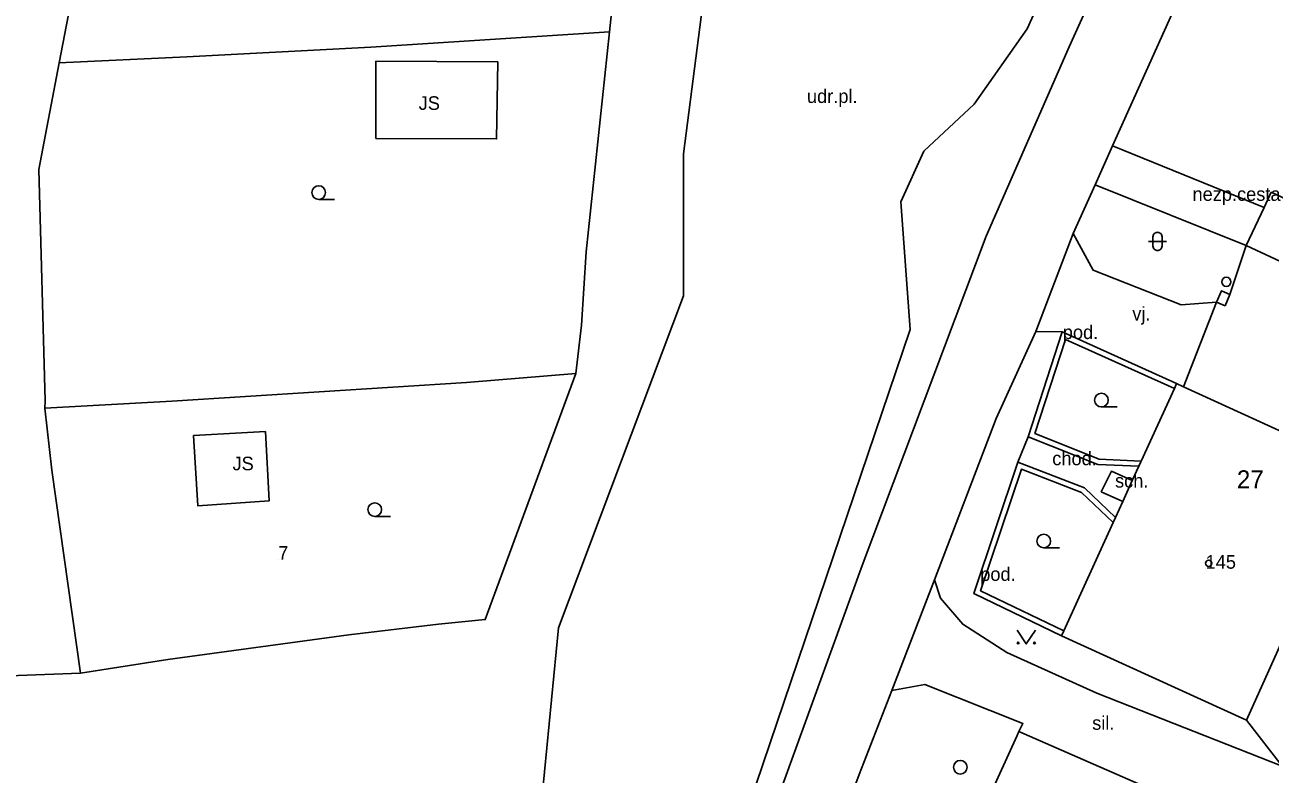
# Model space of a CAD drawing. Extents: x -836739 to -835945, y -1070775 to -1070126.
# Drawn here: x -836690.1 to -836621.5, y -1070440 to -1070398.7 of the extents above; entities that cross this region are included whole.
import ezdxf

# ---------------------------------------------------------------- set-up
doc = ezdxf.new("R2010")
doc.units = 0
for name, color, linetype in [('BodPole_mer', 7, 'Continuous'), ('Budovy_hranice', 7, 'Continuous'), ('Budovy_kody', 7, 'Continuous'), ('Doprava_hranice', 7, 'Continuous'), ('Doprava_kody', 7, 'Continuous'), ('OstPloch_kody', 7, 'Continuous'), ('PovrZnIS_body', 7, 'Continuous'), ('PovrZnIS_hranice', 7, 'Continuous'), ('RuianAdr_popis', 7, 'Continuous'), ('RuianPar_popis', 7, 'Continuous'), ('Stavby_hr_schod', 7, 'Continuous'), ('Stavby_hr_stav', 7, 'Continuous'), ('Stavby_kody', 7, 'Continuous'), ('Stavby_linie', 7, 'Continuous'), ('Zelen_kody', 7, 'Continuous')]:
    doc.layers.add(name, color=color, linetype=linetype)

msp = doc.modelspace()

# ---------------------------------------------------------------- linework, layer by layer
at = {"layer": 'BodPole_mer'}
for p, q in [((-836657.89, -1070399.1), (-836657.89, -1070399.1)), ((-836634.87, -1070398.93), (-836634.87, -1070398.93)), ((-836671.03, -1070399.94), (-836671.03, -1070399.94)), ((-836632.54, -1070399.93), (-836632.54, -1070399.93)), ((-836688.21, -1070400.8), (-836688.21, -1070400.8)), ((-836681.18, -1070400.48), (-836681.18, -1070400.48)), ((-836670.76, -1070400.72), (-836670.76, -1070400.72)), ((-836664.04, -1070400.76), (-836664.04, -1070400.76)), ((-836637.79, -1070403.09), (-836637.79, -1070403.09)), ((-836670.77, -1070404.97), (-836670.77, -1070404.97)), ((-836664.11, -1070405), (-836664.11, -1070405)), ((-836640.55, -1070405.67), (-836640.55, -1070405.67)), ((-836630.16, -1070405.38), (-836630.16, -1070405.38)), ((-836653.8, -1070405.82), (-836653.8, -1070405.82)), ((-836689.33, -1070406.69), (-836689.33, -1070406.69)), ((-836631.12, -1070407.53), (-836631.12, -1070407.53)), ((-836641.83, -1070408.47), (-836641.83, -1070408.47)), ((-836621.81, -1070408.77), (-836621.81, -1070408.77)), ((-836637.13, -1070410.36), (-836637.13, -1070410.36)), ((-836632.33, -1070410.21), (-836632.33, -1070410.21)), ((-836659.17, -1070411.22), (-836659.17, -1070411.22)), ((-836622.8, -1070410.87), (-836622.8, -1070410.87)), ((-836631.23, -1070412.22), (-836631.23, -1070412.22)), ((-836623.89, -1070412.87), (-836623.89, -1070412.87)), ((-836653.8, -1070413.64), (-836653.8, -1070413.64)), ((-836624.42, -1070413.99), (-836624.42, -1070413.99)), ((-836624.15, -1070413.36), (-836624.15, -1070413.36)), ((-836623.69, -1070413.56), (-836623.69, -1070413.56)), ((-836626.38, -1070414.14), (-836626.38, -1070414.14)), ((-836623.96, -1070414.19), (-836623.96, -1070414.19)), ((-836659.43, -1070415.26), (-836659.43, -1070415.26)), ((-836641.31, -1070415.5), (-836641.31, -1070415.5)), ((-836634.38, -1070415.61), (-836634.38, -1070415.61)), ((-836632.93, -1070415.63), (-836632.93, -1070415.63)), ((-836632.75, -1070416.04), (-836632.75, -1070416.04)), ((-836659.73, -1070417.92), (-836659.73, -1070417.92)), ((-836665.77, -1070418.42), (-836665.77, -1070418.42)), ((-836626.75, -1070418.74), (-836626.75, -1070418.74)), ((-836626.63, -1070418.47), (-836626.63, -1070418.47)), ((-836626.24, -1070418.65), (-836626.24, -1070418.65)), ((-836688.98, -1070419.42), (-836688.98, -1070419.42)), ((-836682, -1070419.45), (-836682, -1070419.45)), ((-836689, -1070419.82), (-836689, -1070419.82)), ((-836636.57, -1070420.39), (-836636.57, -1070420.39)), ((-836680.81, -1070421.34), (-836680.81, -1070421.34)), ((-836676.84, -1070421.11), (-836676.84, -1070421.11)), ((-836634.81, -1070421.4), (-836634.81, -1070421.4)), ((-836634.44, -1070421.22), (-836634.44, -1070421.22)), ((-836635.37, -1070422.8), (-836635.37, -1070422.8)), ((-836630.9, -1070422.63), (-836630.9, -1070422.63)), ((-836628.58, -1070422.74), (-836628.58, -1070422.74)), ((-836688.62, -1070423.25), (-836688.62, -1070423.25)), ((-836635.18, -1070423.19), (-836635.18, -1070423.19)), ((-836630.96, -1070422.93), (-836630.96, -1070422.93)), ((-836630.22, -1070423.3), (-836630.22, -1070423.3)), ((-836628.71, -1070423.03), (-836628.71, -1070423.03)), ((-836631.71, -1070424.21), (-836631.71, -1070424.21)), ((-836629.07, -1070423.82), (-836629.07, -1070423.82)), ((-836676.64, -1070424.93), (-836676.64, -1070424.93)), ((-836631.87, -1070424.47), (-836631.87, -1070424.47)), ((-836630.78, -1070424.43), (-836630.78, -1070424.43)), ((-836629.6, -1070424.97), (-836629.6, -1070424.97)), ((-836680.58, -1070425.2), (-836680.58, -1070425.2)), ((-836630.13, -1070426.13), (-836630.13, -1070426.13)), ((-836630, -1070425.84), (-836630, -1070425.84)), ((-836643.96, -1070428.49), (-836643.96, -1070428.49)), ((-836639.98, -1070429.29), (-836639.98, -1070429.29)), ((-836639.64, -1070430.3), (-836639.64, -1070430.3)), ((-836637.8, -1070430.04), (-836637.8, -1070430.04)), ((-836637.43, -1070429.88), (-836637.43, -1070429.88)), ((-836667.3, -1070431.72), (-836667.3, -1070431.72)), ((-836664.73, -1070431.47), (-836664.73, -1070431.47)), ((-836638.41, -1070431.73), (-836638.41, -1070431.73)), ((-836672.25, -1070432.32), (-836672.25, -1070432.32)), ((-836660.69, -1070431.93), (-836660.69, -1070431.93)), ((-836632.97, -1070432.36), (-836632.97, -1070432.36)), ((-836632.85, -1070432.09), (-836632.85, -1070432.09)), ((-836682.22, -1070433.67), (-836682.22, -1070433.67)), ((-836635.98, -1070433.29), (-836635.98, -1070433.29)), ((-836687.04, -1070434.42), (-836687.04, -1070434.42)), ((-836640.5, -1070435.05), (-836640.5, -1070435.05)), ((-836642.32, -1070435.38), (-836642.32, -1070435.38)), ((-836631.03, -1070435.52), (-836631.03, -1070435.52)), ((-836635.1, -1070437.2), (-836635.1, -1070437.2)), ((-836622.78, -1070437.01), (-836622.78, -1070437.01)), ((-836635.42, -1070437.86), (-836635.42, -1070437.86)), ((-836635.32, -1070437.63), (-836635.32, -1070437.63))]:
    msp.add_line(p, q, dxfattribs=at)
at = {"layer": 'Budovy_hranice'}
for p, q in [((-836632.97, -1070432.36), (-836622.78, -1070437.01)), ((-836622.29, -1070443.32), (-836635.32, -1070437.63))]:
    msp.add_line(p, q, dxfattribs=at)
for points in [[(-836626.63, -1070418.47), (-836626.75, -1070418.74), (-836628.58, -1070422.74), (-836628.71, -1070423.03), (-836629.07, -1070423.82), (-836629.6, -1070424.97), (-836630, -1070425.84), (-836630.13, -1070426.13), (-836632.85, -1070432.09), (-836632.97, -1070432.36)], [(-836616.52, -1070423.1), (-836626.24, -1070418.65), (-836626.63, -1070418.47)], [(-836616.52, -1070423.1), (-836616.66, -1070423.42), (-836618.95, -1070428.51), (-836619.49, -1070429.7), (-836622.78, -1070437.01)], [(-836635.32, -1070437.63), (-836635.42, -1070437.86), (-836637.6, -1070442.65), (-836637.7, -1070442.88), (-836637.98, -1070443.48)]]:
    msp.add_lwpolyline(points, dxfattribs=at)
at = {"layer": 'Budovy_kody'}
msp.add_circle((-836624.86, -1070428.37), 0.175, dxfattribs=at)
at = {"layer": 'Doprava_hranice'}
for p, q in [((-836621.81, -1070408.77), (-836630.16, -1070405.38)), ((-836622.8, -1070410.87), (-836631.12, -1070407.53)), ((-836632.93, -1070415.63), (-836634.38, -1070415.61))]:
    msp.add_line(p, q, dxfattribs=at)
for points in [[(-836637.13, -1070410.36), (-836632.54, -1070399.93), (-836624.1, -1070381.23), (-836615.6, -1070365.58), (-836607.14, -1070355.56), (-836596.81, -1070346.2), (-836590.03, -1070339.5), (-836589.31, -1070338.79), (-836589.07, -1070337.69), (-836589.06, -1070336.43), (-836589.28, -1070334.96), (-836590.73, -1070333.14), (-836591.73, -1070332.35), (-836593.66, -1070331.61), (-836605.86, -1070329.36), (-836624.31, -1070324.48)], [(-836629.46, -1070381.04), (-836630.1, -1070382.38), (-836632.83, -1070381.55), (-836636.09, -1070386.19), (-836641.48, -1070386.97), (-836650.79, -1070382.45), (-836653.8, -1070405.82), (-836653.8, -1070413.64), (-836660.69, -1070431.93), (-836661.86, -1070443.82), (-836659.27, -1070448.73), (-836656.69, -1070455.24), (-836654.9, -1070458.11)], [(-836626.49, -1070382.25), (-836628.93, -1070385.76), (-836634.87, -1070398.93), (-836637.79, -1070403.09), (-836640.55, -1070405.67), (-836641.83, -1070408.47), (-836641.31, -1070415.5), (-836651.36, -1070445.15), (-836654.9, -1070458.11), (-836657.15, -1070469.1)], [(-836636.57, -1070420.39), (-836634.38, -1070415.61), (-836632.33, -1070410.21), (-836631.12, -1070407.53), (-836630.16, -1070405.38), (-836624, -1070391.72)], [(-836649.35, -1070443.39), (-836643.96, -1070428.49), (-836637.13, -1070410.36)], [(-836624.42, -1070413.99), (-836626.38, -1070414.14), (-836631.23, -1070412.22), (-836632.33, -1070410.21)], [(-836636.57, -1070420.39), (-836639.98, -1070429.29), (-836642.32, -1070435.38), (-836644.12, -1070440), (-836644.66, -1070441.44), (-836645.98, -1070445.15)], [(-836620.81, -1070439.55), (-836631.03, -1070435.52), (-836635.98, -1070433.29), (-836638.41, -1070431.73), (-836639.64, -1070430.3), (-836639.98, -1070429.29)], [(-836642.32, -1070435.38), (-836640.5, -1070435.05), (-836635.1, -1070437.2), (-836635.32, -1070437.63)]]:
    msp.add_lwpolyline(points, dxfattribs=at)
at = {"layer": 'OstPloch_kody'}
for p, q in [((-836673.035, -1070408.33), (-836673.91, -1070408.33)), ((-836627.93, -1070410.89), (-836627.93, -1070410.39)), ((-836627.43, -1070410.39), (-836627.43, -1070410.89)), ((-836628.18, -1070410.64), (-836627.18, -1070410.64)), ((-836629.895, -1070419.76), (-836630.77, -1070419.76)), ((-836669.945, -1070425.79), (-836670.82, -1070425.79)), ((-836633.075, -1070427.52), (-836633.95, -1070427.52))]:
    msp.add_line(p, q, dxfattribs=at)
for points in [[(-836627.68, -1070410.14), (-836627.725, -1070410.144), (-836627.772, -1070410.158), (-836627.817, -1070410.181), (-836627.857, -1070410.213), (-836627.889, -1070410.253), (-836627.912, -1070410.298), (-836627.926, -1070410.345), (-836627.93, -1070410.39)], [(-836627.68, -1070410.14), (-836627.635, -1070410.144), (-836627.588, -1070410.158), (-836627.543, -1070410.181), (-836627.503, -1070410.213), (-836627.471, -1070410.253), (-836627.448, -1070410.298), (-836627.434, -1070410.345), (-836627.43, -1070410.39)], [(-836627.68, -1070411.14), (-836627.725, -1070411.136), (-836627.772, -1070411.122), (-836627.817, -1070411.099), (-836627.857, -1070411.067), (-836627.889, -1070411.027), (-836627.912, -1070410.982), (-836627.926, -1070410.935), (-836627.93, -1070410.89)], [(-836627.43, -1070410.89), (-836627.434, -1070410.935), (-836627.448, -1070410.982), (-836627.471, -1070411.027), (-836627.503, -1070411.067), (-836627.543, -1070411.099), (-836627.588, -1070411.122), (-836627.635, -1070411.136), (-836627.68, -1070411.14)]]:
    msp.add_lwpolyline(points, dxfattribs=at)
for centre in [(-836673.91, -1070407.955), (-836630.77, -1070419.385), (-836670.82, -1070425.415), (-836633.95, -1070427.145), (-836638.55, -1070439.605)]:
    msp.add_ellipse(centre, major_axis=(0.375, 0), ratio=0.999999, dxfattribs=at)
at = {"layer": 'PovrZnIS_body'}
msp.add_circle((-836623.89, -1070412.87), 0.25, dxfattribs=at)
at = {"layer": 'PovrZnIS_hranice'}
for p, q in [((-836624.15, -1070413.36), (-836624.42, -1070413.99)), ((-836623.96, -1070414.19), (-836624.42, -1070413.99)), ((-836623.69, -1070413.56), (-836624.15, -1070413.36)), ((-836623.69, -1070413.56), (-836623.96, -1070414.19))]:
    msp.add_line(p, q, dxfattribs=at)
at = {"layer": 'RuianAdr_popis'}
msp.add_line((-836623.31, -1070424.25), (-836623.31, -1070424.25), dxfattribs=at)
at = {"layer": 'RuianPar_popis'}
for p, q in [((-836676.14, -1070428.17), (-836676.14, -1070428.17)), ((-836625.03, -1070428.67), (-836625.03, -1070428.67))]:
    msp.add_line(p, q, dxfattribs=at)
at = {"layer": 'Stavby_hr_schod'}
msp.add_lwpolyline([(-836629.6, -1070424.97), (-836630.78, -1070424.43), (-836630.22, -1070423.3), (-836629.07, -1070423.82)], dxfattribs=at)
at = {"layer": 'Stavby_hr_stav'}
for p, q in [((-836670.77, -1070404.97), (-836670.76, -1070400.72)), ((-836670.76, -1070400.72), (-836664.04, -1070400.76))]:
    msp.add_line(p, q, dxfattribs=at)
for points in [[(-836670.77, -1070404.97), (-836664.11, -1070405), (-836664.04, -1070400.76)], [(-836621.42, -1070407.93), (-836614.41, -1070411.21), (-836615.78, -1070414.14), (-836622.8, -1070410.87), (-836621.81, -1070408.77), (-836621.42, -1070407.93)], [(-836626.63, -1070418.47), (-836632.93, -1070415.63), (-836634.81, -1070421.4), (-836630.96, -1070422.93), (-836628.71, -1070423.03)], [(-836676.84, -1070421.11), (-836676.64, -1070424.93), (-836680.58, -1070425.2), (-836680.81, -1070421.34), (-836676.84, -1070421.11)], [(-836630, -1070425.84), (-836631.71, -1070424.21), (-836635.37, -1070422.8), (-836637.8, -1070430.04), (-836632.97, -1070432.36)]]:
    msp.add_lwpolyline(points, dxfattribs=at)
at = {"layer": 'Stavby_linie'}
for p, q in [((-836626.24, -1070418.65), (-836624.42, -1070413.99)), ((-836634.81, -1070421.4), (-836635.37, -1070422.8)), ((-836622.78, -1070437.01), (-836620.81, -1070439.55))]:
    msp.add_line(p, q, dxfattribs=at)
for points in [[(-836659.17, -1070411.22), (-836657.89, -1070399.1), (-836657.04, -1070391.1), (-836655.87, -1070380.69)], [(-836686.61, -1070391.4), (-836687.61, -1070397.67), (-836688.21, -1070400.8), (-836689.33, -1070406.69), (-836688.98, -1070419.42), (-836689, -1070419.82)], [(-836688.21, -1070400.8), (-836681.18, -1070400.48), (-836671.03, -1070399.94), (-836657.89, -1070399.1)], [(-836687.04, -1070434.42), (-836682.22, -1070433.67), (-836672.25, -1070432.32), (-836667.3, -1070431.72), (-836664.73, -1070431.47), (-836659.73, -1070417.92), (-836659.43, -1070415.26), (-836659.17, -1070411.22)], [(-836622.8, -1070410.87), (-836623.69, -1070413.56), (-836624.15, -1070413.36), (-836624.42, -1070413.99)], [(-836626.75, -1070418.74), (-836632.75, -1070416.04), (-836634.44, -1070421.22), (-836630.9, -1070422.63), (-836628.58, -1070422.74)], [(-836687.04, -1070434.42), (-836688.62, -1070423.25), (-836689, -1070419.82), (-836682, -1070419.45), (-836665.77, -1070418.42), (-836659.73, -1070417.92)], [(-836630.13, -1070426.13), (-836631.87, -1070424.47), (-836635.18, -1070423.19), (-836637.43, -1070429.88), (-836632.85, -1070432.09)], [(-836702.58, -1070435.01), (-836702.27, -1070435), (-836687.04, -1070434.42)]]:
    msp.add_lwpolyline(points, dxfattribs=at)
at = {"layer": 'Zelen_kody'}
msp.add_lwpolyline([(-836634.41, -1070432.06), (-836634.91, -1070432.81), (-836635.41, -1070432.06)], dxfattribs=at)
for centre in [(-836635.359, -1070432.76), (-836634.459, -1070432.76)]:
    msp.add_circle(centre, 0.05, dxfattribs=at)

# ---------------------------------------------------------------- texts
at = {"layer": 'Doprava_kody'}
for s, p in [('nezp.cesta', (-836625.75, -1070408.41)), ('vj.', (-836629.07, -1070415)), ('chod.', (-836633.48, -1070422.97)), ('sil.', (-836631.28, -1070437.54))]:
    msp.add_text(s, height=0.75, dxfattribs=at).set_placement(p)
at = {"layer": 'RuianAdr_popis'}
msp.add_text('27', height=1, dxfattribs=at).set_placement((-836623.31, -1070424.25))
at = {"layer": 'RuianPar_popis'}
for s, p in [('7', (-836676.14, -1070428.17)), ('145', (-836625.03, -1070428.67))]:
    msp.add_text(s, height=0.75, dxfattribs=at).set_placement(p)
at = {"layer": 'Stavby_kody'}
for s, p in [('JS', (-836668.4, -1070403.4)), ('pod.', (-836632.9, -1070416.02)), ('JS', (-836678.66, -1070423.25)), ('sch.', (-836630.02, -1070424.2)), ('pod.', (-836637.45, -1070429.34))]:
    msp.add_text(s, height=0.75, dxfattribs=at).set_placement(p)
at = {"layer": 'Zelen_kody'}
msp.add_text('udr.pl.', height=0.75, dxfattribs=at).set_placement((-836647, -1070403.02))

doc.saveas('drawing.dxf')
